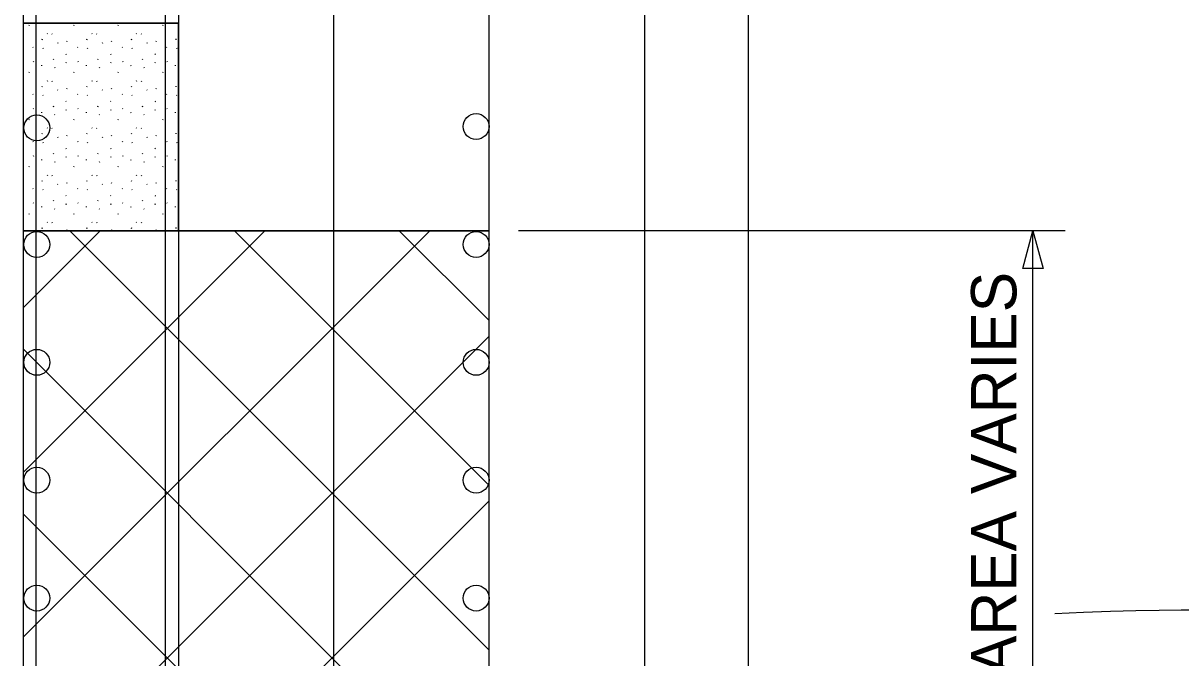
# Model space of a CAD drawing. Extents: x 16732 to 18475, y 5726 to 6929.
# Drawn here: x 17049.4 to 17228.2, y 6629.8 to 6727.8 of the extents above; entities that cross this region are included whole.
import ezdxf

# ---------------------------------------------------------------- set-up
doc = ezdxf.new("R2010")
doc.units = 0
for name, color, linetype in [('ALI_LEGAL_EX', 7, 'Continuous'), ('MT_SCRATCH_LEVEL_A', 7, 'Continuous'), ('PAVT_EDGE_EX', 7, 'Continuous'), ('TRAFFIC_SIGNS_PR', 7, 'Continuous'), ('TYPICAL_TEXT_DIMEN_PR', 7, 'Continuous')]:
    doc.layers.add(name, color=color, linetype=linetype)

msp = doc.modelspace()

# ---------------------------------------------------------------- linework, layer by layer
at = {"layer": 'ALI_LEGAL_EX'}
for p, q in [((17051.36, 6131.68), (17051.36, 6928.96)), ((17071.36, 6131.68), (17071.36, 6928.96)), ((17097.36, 6131.68), (17097.36, 6928.96)), ((17121.36, 6131.68), (17121.36, 6928.96))]:
    msp.add_line(p, q, dxfattribs=at)
for points in [[(17051.36, 6631.68), (17051.36, 6656.68)], [(17071.36, 6631.68), (17071.36, 6656.68)], [(17097.36, 6631.68), (17097.36, 6656.68)], [(17121.36, 6631.68), (17121.36, 6656.68)]]:
    msp.add_lwpolyline(points, dxfattribs=at)
at = {"layer": 'MT_SCRATCH_LEVEL_A'}
for p, q in [((17049.36, 6727.81), (17073.36, 6727.81)), ((17049.36, 6727.81), (17049.36, 6549.97)), ((17073.36, 6727.81), (17049.36, 6727.81)), ((17049.36, 6727.81), (17049.36, 6695.75)), ((17050.28, 6727.45), (17050.33, 6727.57)), ((17057.17, 6727.45), (17057.22, 6727.57)), ((17064.06, 6727.45), (17064.11, 6727.57)), ((17070.95, 6727.45), (17071, 6727.57)), ((17073.36, 6727.81), (17073.36, 6695.75)), ((17073.36, 6695.75), (17073.36, 6727.81)), ((17052.3, 6725.25), (17052.35, 6725.37)), ((17053.07, 6726.21), (17053.12, 6726.14)), ((17053.8, 6726.19), (17053.86, 6726.11)), ((17056.12, 6724.96), (17056.17, 6725.07)), ((17059.19, 6725.25), (17059.24, 6725.37)), ((17059.96, 6726.21), (17060.01, 6726.14)), ((17060.69, 6726.19), (17060.74, 6726.11)), ((17063.01, 6724.96), (17063.06, 6725.07)), ((17066.08, 6725.25), (17066.13, 6725.37)), ((17066.84, 6726.21), (17066.89, 6726.14)), ((17067.58, 6726.19), (17067.63, 6726.11)), ((17069.9, 6724.96), (17069.95, 6725.07)), ((17072.97, 6725.25), (17073.02, 6725.37)), ((17050.85, 6724.13), (17050.9, 6724.05)), ((17052.38, 6723.99), (17052.44, 6723.91)), ((17054.67, 6724.81), (17054.72, 6724.73)), ((17057.74, 6724.13), (17057.79, 6724.05)), ((17059.27, 6723.99), (17059.32, 6723.91)), ((17061.56, 6724.81), (17061.61, 6724.73)), ((17064.63, 6724.13), (17064.68, 6724.05)), ((17066.16, 6723.99), (17066.21, 6723.91)), ((17068.45, 6724.81), (17068.5, 6724.73)), ((17071.52, 6724.13), (17071.57, 6724.05)), ((17073.05, 6723.99), (17073.1, 6723.91)), ((17050.9, 6721.92), (17050.95, 6721.84)), ((17052.18, 6721.34), (17052.2, 6721.23)), ((17054.03, 6722.2), (17054.08, 6722.32)), ((17055.95, 6723.07), (17056, 6722.99)), ((17055.99, 6721.67), (17056.04, 6721.78)), ((17057.79, 6721.92), (17057.84, 6721.84)), ((17059.07, 6721.34), (17059.08, 6721.23)), ((17060.91, 6722.2), (17060.96, 6722.32)), ((17062.84, 6723.07), (17062.89, 6722.99)), ((17062.88, 6721.67), (17062.93, 6721.78)), ((17064.68, 6721.92), (17064.73, 6721.84)), ((17065.96, 6721.34), (17065.97, 6721.23)), ((17067.8, 6722.2), (17067.85, 6722.32)), ((17069.72, 6723.07), (17069.78, 6722.99)), ((17069.77, 6721.67), (17069.82, 6721.78)), ((17071.56, 6721.92), (17071.62, 6721.84)), ((17072.85, 6721.34), (17072.86, 6721.23)), ((17050.28, 6720.17), (17050.33, 6720.28)), ((17054.21, 6721), (17054.26, 6720.92)), ((17057.17, 6720.17), (17057.22, 6720.28)), ((17061.1, 6721), (17061.15, 6720.92)), ((17064.06, 6720.17), (17064.11, 6720.28)), ((17067.99, 6721), (17068.04, 6720.92)), ((17070.95, 6720.17), (17071, 6720.28)), ((17052.3, 6717.97), (17052.35, 6718.09)), ((17053.07, 6718.93), (17053.12, 6718.85)), ((17053.8, 6718.9), (17053.86, 6718.82)), ((17056.12, 6717.67), (17056.17, 6717.79)), ((17059.19, 6717.97), (17059.24, 6718.09)), ((17059.96, 6718.93), (17060.01, 6718.85)), ((17060.69, 6718.9), (17060.74, 6718.82)), ((17063.01, 6717.67), (17063.06, 6717.79)), ((17066.08, 6717.97), (17066.13, 6718.09)), ((17066.84, 6718.93), (17066.89, 6718.85)), ((17067.58, 6718.9), (17067.63, 6718.82)), ((17069.9, 6717.67), (17069.95, 6717.79)), ((17072.97, 6717.97), (17073.02, 6718.09)), ((17050.85, 6716.84), (17050.9, 6716.77)), ((17052.38, 6716.7), (17052.44, 6716.62)), ((17054.67, 6717.52), (17054.72, 6717.44)), ((17057.74, 6716.84), (17057.79, 6716.77)), ((17059.27, 6716.7), (17059.32, 6716.62)), ((17061.56, 6717.52), (17061.61, 6717.44)), ((17064.63, 6716.84), (17064.68, 6716.77)), ((17066.16, 6716.7), (17066.21, 6716.62)), ((17068.45, 6717.52), (17068.5, 6717.44)), ((17071.52, 6716.84), (17071.57, 6716.77)), ((17073.05, 6716.7), (17073.1, 6716.62)), ((17050.9, 6714.63), (17050.95, 6714.56)), ((17054.03, 6714.91), (17054.08, 6715.03)), ((17055.95, 6715.78), (17056, 6715.71)), ((17055.99, 6714.38), (17056.04, 6714.5)), ((17057.79, 6714.63), (17057.84, 6714.56)), ((17060.91, 6714.91), (17060.96, 6715.03)), ((17062.84, 6715.78), (17062.89, 6715.71)), ((17062.88, 6714.38), (17062.93, 6714.5)), ((17064.68, 6714.63), (17064.73, 6714.56)), ((17067.8, 6714.91), (17067.85, 6715.03)), ((17069.72, 6715.78), (17069.78, 6715.71)), ((17069.77, 6714.38), (17069.82, 6714.5)), ((17071.56, 6714.63), (17071.62, 6714.56)), ((17050.28, 6712.88), (17050.33, 6713)), ((17052.18, 6714.06), (17052.2, 6713.94)), ((17054.21, 6713.72), (17054.26, 6713.64)), ((17057.17, 6712.88), (17057.22, 6713)), ((17059.07, 6714.06), (17059.08, 6713.94)), ((17061.1, 6713.72), (17061.15, 6713.64)), ((17064.06, 6712.88), (17064.11, 6713)), ((17065.96, 6714.06), (17065.97, 6713.94)), ((17067.99, 6713.72), (17068.04, 6713.64)), ((17070.95, 6712.88), (17071, 6713)), ((17072.85, 6714.06), (17072.86, 6713.94)), ((17052.3, 6710.69), (17052.35, 6710.8)), ((17053.07, 6711.64), (17053.12, 6711.57)), ((17053.8, 6711.61), (17053.86, 6711.54)), ((17059.19, 6710.69), (17059.24, 6710.8)), ((17059.96, 6711.64), (17060.01, 6711.57)), ((17060.69, 6711.61), (17060.74, 6711.54)), ((17066.08, 6710.69), (17066.13, 6710.8)), ((17066.84, 6711.64), (17066.89, 6711.57)), ((17067.58, 6711.61), (17067.63, 6711.54)), ((17072.97, 6710.69), (17073.02, 6710.8)), ((17050.85, 6709.56), (17050.9, 6709.48)), ((17052.38, 6709.42), (17052.44, 6709.34)), ((17054.67, 6710.24), (17054.72, 6710.16)), ((17056.12, 6710.39), (17056.17, 6710.5)), ((17057.74, 6709.56), (17057.79, 6709.48)), ((17059.27, 6709.42), (17059.32, 6709.34)), ((17061.56, 6710.24), (17061.61, 6710.16)), ((17063.01, 6710.39), (17063.06, 6710.5)), ((17064.63, 6709.56), (17064.68, 6709.48)), ((17066.16, 6709.42), (17066.21, 6709.34)), ((17068.45, 6710.24), (17068.5, 6710.16)), ((17069.9, 6710.39), (17069.95, 6710.5)), ((17071.52, 6709.56), (17071.57, 6709.48)), ((17073.05, 6709.42), (17073.1, 6709.34)), ((17050.9, 6707.35), (17050.95, 6707.27)), ((17054.03, 6707.63), (17054.08, 6707.75)), ((17055.95, 6708.5), (17056, 6708.42)), ((17055.99, 6707.1), (17056.04, 6707.22)), ((17057.79, 6707.35), (17057.84, 6707.27)), ((17060.91, 6707.63), (17060.96, 6707.75)), ((17062.84, 6708.5), (17062.89, 6708.42)), ((17062.88, 6707.1), (17062.93, 6707.22)), ((17064.68, 6707.35), (17064.73, 6707.27)), ((17067.8, 6707.63), (17067.85, 6707.75)), ((17069.72, 6708.5), (17069.78, 6708.42)), ((17069.77, 6707.1), (17069.82, 6707.22)), ((17071.56, 6707.35), (17071.62, 6707.27)), ((17050.28, 6705.6), (17050.33, 6705.71)), ((17052.18, 6706.77), (17052.2, 6706.66)), ((17054.21, 6706.43), (17054.26, 6706.35)), ((17057.17, 6705.6), (17057.22, 6705.71)), ((17059.07, 6706.77), (17059.08, 6706.66)), ((17061.1, 6706.43), (17061.15, 6706.35)), ((17064.06, 6705.6), (17064.11, 6705.71)), ((17065.96, 6706.77), (17065.97, 6706.66)), ((17067.99, 6706.43), (17068.04, 6706.35)), ((17070.95, 6705.6), (17071, 6705.71)), ((17072.85, 6706.77), (17072.86, 6706.66)), ((17052.3, 6703.4), (17052.35, 6703.52)), ((17053.07, 6704.36), (17053.12, 6704.28)), ((17053.8, 6704.33), (17053.86, 6704.25)), ((17059.19, 6703.4), (17059.24, 6703.52)), ((17059.96, 6704.36), (17060.01, 6704.28)), ((17060.69, 6704.33), (17060.74, 6704.25)), ((17066.08, 6703.4), (17066.13, 6703.52)), ((17066.84, 6704.36), (17066.89, 6704.28)), ((17067.58, 6704.33), (17067.63, 6704.25)), ((17072.97, 6703.4), (17073.02, 6703.52)), ((17050.85, 6702.27), (17050.9, 6702.2)), ((17052.38, 6702.13), (17052.44, 6702.06)), ((17054.67, 6702.95), (17054.72, 6702.87)), ((17056.12, 6703.1), (17056.17, 6703.22)), ((17057.74, 6702.27), (17057.79, 6702.2)), ((17059.27, 6702.13), (17059.32, 6702.06)), ((17061.56, 6702.95), (17061.61, 6702.87)), ((17063.01, 6703.1), (17063.06, 6703.22)), ((17064.63, 6702.27), (17064.68, 6702.2)), ((17066.16, 6702.13), (17066.21, 6702.06)), ((17068.45, 6702.95), (17068.5, 6702.87)), ((17069.9, 6703.1), (17069.95, 6703.22)), ((17071.52, 6702.27), (17071.57, 6702.2)), ((17073.05, 6702.13), (17073.1, 6702.06)), ((17050.9, 6700.06), (17050.95, 6699.99)), ((17054.03, 6700.34), (17054.08, 6700.46)), ((17055.95, 6701.21), (17056, 6701.14)), ((17055.99, 6699.81), (17056.04, 6699.93)), ((17057.79, 6700.06), (17057.84, 6699.99)), ((17060.91, 6700.34), (17060.96, 6700.46)), ((17062.84, 6701.21), (17062.89, 6701.14)), ((17062.88, 6699.81), (17062.93, 6699.93)), ((17064.68, 6700.06), (17064.73, 6699.99)), ((17067.8, 6700.34), (17067.85, 6700.46)), ((17069.72, 6701.21), (17069.78, 6701.14)), ((17069.77, 6699.81), (17069.82, 6699.93)), ((17071.56, 6700.06), (17071.62, 6699.99)), ((17050.28, 6698.31), (17050.33, 6698.43)), ((17052.18, 6699.49), (17052.2, 6699.37)), ((17054.21, 6699.15), (17054.26, 6699.07)), ((17057.17, 6698.31), (17057.22, 6698.43)), ((17059.07, 6699.49), (17059.08, 6699.37)), ((17061.1, 6699.15), (17061.15, 6699.07)), ((17064.06, 6698.31), (17064.11, 6698.43)), ((17065.96, 6699.49), (17065.97, 6699.37)), ((17067.99, 6699.15), (17068.04, 6699.07)), ((17070.95, 6698.31), (17071, 6698.43)), ((17072.85, 6699.49), (17072.86, 6699.37)), ((17053.07, 6697.07), (17053.12, 6697)), ((17053.8, 6697.05), (17053.86, 6696.97)), ((17059.96, 6697.07), (17060.01, 6697)), ((17060.69, 6697.05), (17060.74, 6696.97)), ((17066.84, 6697.07), (17066.89, 6697)), ((17067.58, 6697.05), (17067.63, 6696.97)), ((17049.36, 6695.75), (17121.36, 6695.75)), ((17121.36, 6695.75), (17049.36, 6695.75)), ((17049.36, 6695.75), (17049.36, 6582.03)), ((17049.36, 6695.75), (17073.36, 6695.75)), ((17049.36, 6683.85), (17061.26, 6695.75)), ((17049.36, 6658.39), (17086.71, 6695.75)), ((17049.36, 6632.94), (17112.17, 6695.75)), ((17052.3, 6696.11), (17052.35, 6696.23)), ((17056.12, 6695.82), (17056.17, 6695.93)), ((17121.36, 6630.94), (17056.55, 6695.75)), ((17059.19, 6696.11), (17059.24, 6696.23)), ((17063.01, 6695.82), (17063.06, 6695.93)), ((17066.08, 6696.11), (17066.13, 6696.23)), ((17069.9, 6695.82), (17069.95, 6695.93)), ((17072.97, 6696.11), (17073.02, 6696.23)), ((17121.36, 6656.4), (17082, 6695.75)), ((17121.36, 6681.85), (17107.46, 6695.75)), ((17049.36, 6607.48), (17121.36, 6679.48)), ((17121.36, 6605.48), (17049.36, 6677.48)), ((17049.36, 6582.03), (17121.36, 6654.03)), ((17119.36, 6582.03), (17049.36, 6652.03))]:
    msp.add_line(p, q, dxfattribs=at)
at = {"layer": 'PAVT_EDGE_EX'}
for p, q in [((17049.36, 6924.76), (17049.36, 6059.7)), ((17073.36, 6924.76), (17073.36, 6059.7)), ((17145.36, 6924.76), (17145.36, 6059.7)), ((17161.36, 6924.76), (17161.36, 6059.7))]:
    msp.add_line(p, q, dxfattribs=at)
at = {"layer": 'TRAFFIC_SIGNS_PR'}
for centre in [(17051.46, 6711.63), (17119.33, 6711.84), (17051.46, 6693.63), (17119.33, 6693.63), (17051.46, 6675.41), (17119.33, 6675.41), (17051.46, 6657.2), (17119.33, 6657.2), (17051.46, 6638.99), (17119.33, 6638.99)]:
    msp.add_circle(centre, 2, dxfattribs=at)
at = {"layer": 'TYPICAL_TEXT_DIMEN_PR'}
for p, q in [((17210.36, 6695.75), (17125.86, 6695.75)), ((17203.79, 6689.89), (17205.36, 6695.75)), ((17205.36, 6582.03), (17205.36, 6695.75)), ((17205.36, 6695.75), (17206.93, 6689.89)), ((17205.36, 6689.89), (17203.79, 6689.89)), ((17206.93, 6689.89), (17205.36, 6689.89))]:
    msp.add_line(p, q, dxfattribs=at)
msp.add_open_spline([(17208.74, 6636.6), (17257.65, 6638.89), (17257.65, 6628.28), (17222.32, 6628.28), (17222.32, 6617.27), (17265.17, 6616.02), (17276.52, 6616.04)], degree=3, dxfattribs=at)

# ---------------------------------------------------------------- texts
msp.add_text('WORK AREA VARIES', height=7, rotation=90, dxfattribs=at).set_placement((17202.8, 6595.24))

doc.saveas('drawing.dxf')
